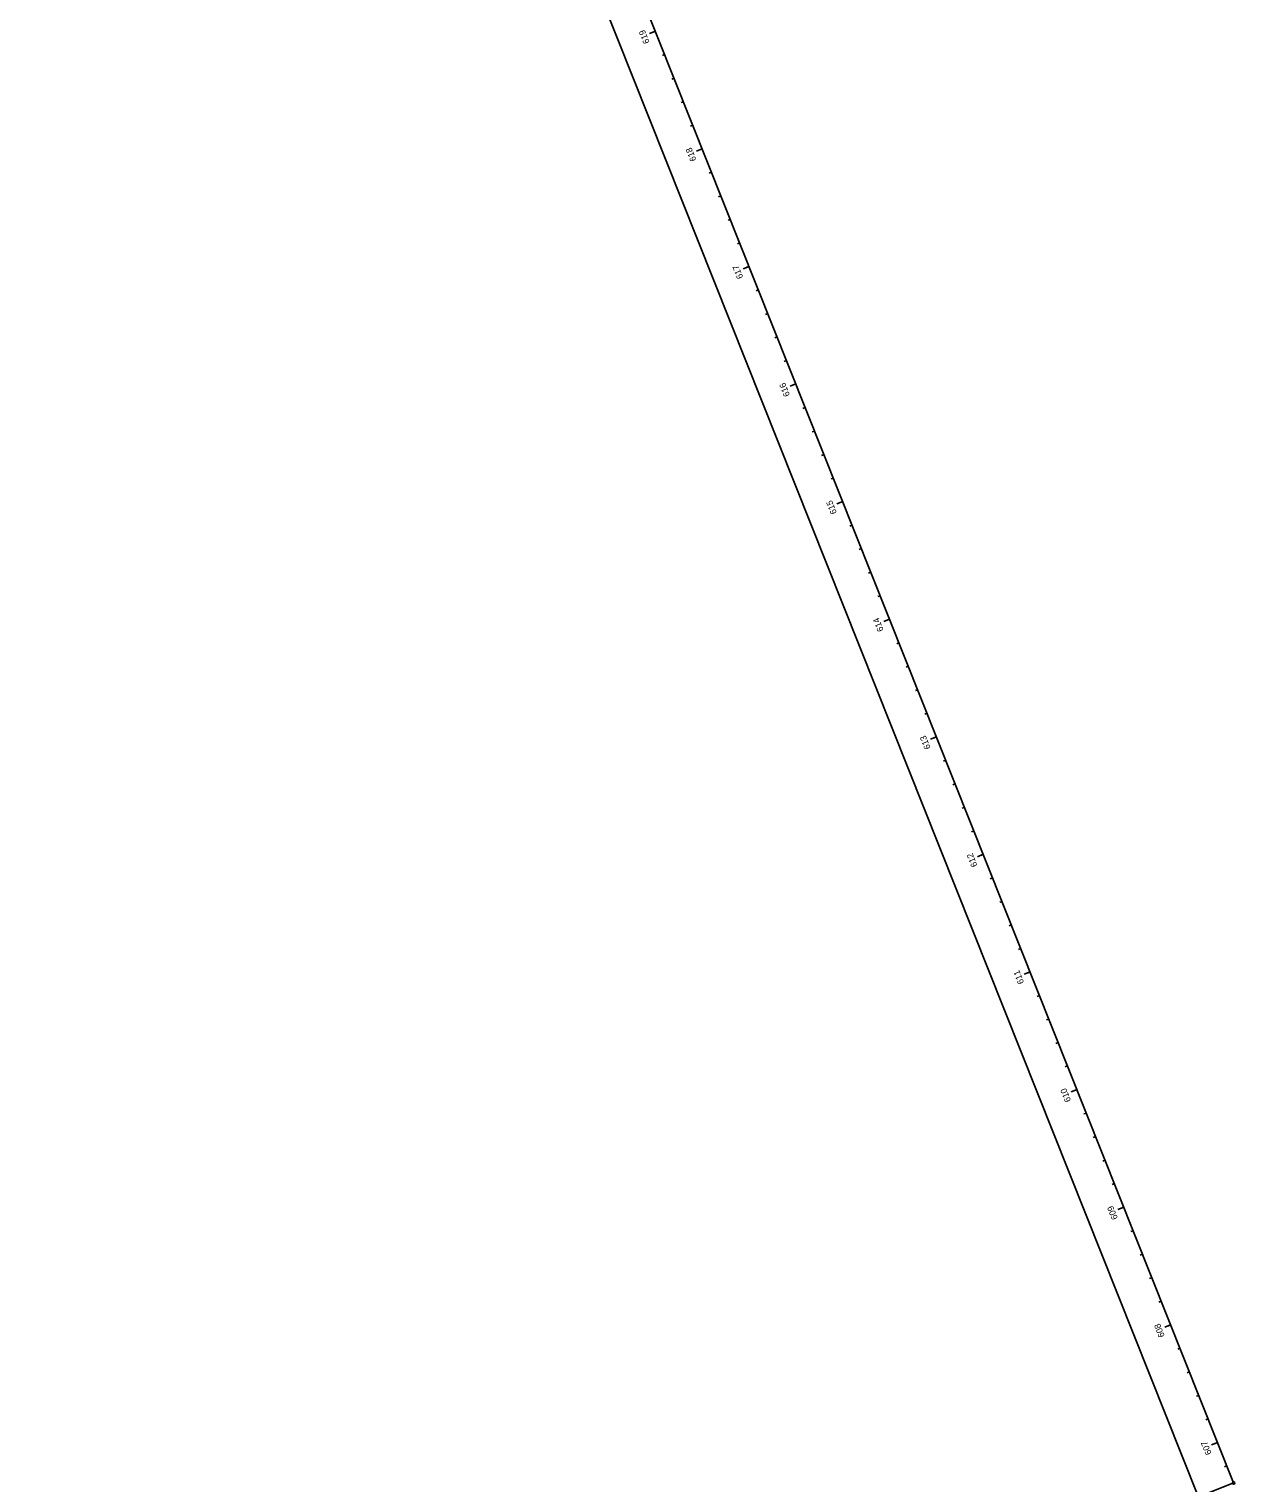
# Model space of a CAD drawing. Extents: x 2003883 to 2007688, y 399149 to 412300.
# Drawn here: x 2004016 to 2004969, y 407935 to 409083 of the extents above; entities that cross this region are included whole.
import ezdxf

# ---------------------------------------------------------------- set-up
doc = ezdxf.new("R2010")
doc.units = 0
for name, color, linetype in [('BaselineSurvey', 7, 'Continuous'), ('DataBoxWt2', 7, 'Continuous'), ('Default', 7, 'Continuous'), ('EaseLine_ep', 7, 'Continuous'), ('PropertyLine_ep', 7, 'Continuous'), ('PropertyLineHook_ep', 7, 'Continuous'), ('PropertyLineSymbol_ep', 7, 'Continuous'), ('SubDivLineText', 7, 'Continuous'), ('SubLotNumberText', 7, 'Continuous'), ('SubVacOrigLotStaTie', 7, 'Continuous'), ('TextMisc', 7, 'Continuous')]:
    doc.layers.add(name, color=color, linetype=linetype)

msp = doc.modelspace()

# ---------------------------------------------------------------- linework, layer by layer
at = {"layer": 'DataBoxWt2'}
for p, q in [((2004547.7, 408988.9), (2004545.9, 408988.2)), ((2004621.8, 408803.2), (2004619.9, 408802.4)), ((2004695.8, 408617.4), (2004694, 408616.6)), ((2004769.8, 408431.6), (2004768, 408430.8)), ((2004843.9, 408245.8), (2004839.2, 408243.9)), ((2004917.9, 408060), (2004916.1, 408059.2))]:
    msp.add_line(p, q, dxfattribs=at)
at = {"layer": 'Default'}
msp.add_line((2004967.7, 407935), (2004043.6, 410254), dxfattribs=at)
at = {"layer": 'EaseLine_ep'}
msp.add_line((2004939.8, 407923.9), (2004015.7, 410242.9), dxfattribs=at)
at = {"layer": 'PropertyLine_ep'}
msp.add_line((2004967.7, 407935), (2004043.6, 410254), dxfattribs=at)
at = {"layer": 'PropertyLineHook_ep'}
for p, q in [((2004510.7, 409081.8), (2004506.1, 409080)), ((2004518.1, 409063.3), (2004516.3, 409062.5)), ((2004525.5, 409044.7), (2004523.7, 409043.9)), ((2004532.9, 409026.1), (2004531.1, 409025.4)), ((2004540.3, 409007.5), (2004538.5, 409006.8)), ((2004547.7, 408988.9), (2004543.1, 408987.1)), ((2004555.1, 408970.4), (2004553.3, 408969.6)), ((2004562.5, 408951.8), (2004560.7, 408951)), ((2004569.9, 408933.2), (2004568.1, 408932.5)), ((2004577.4, 408914.6), (2004575.5, 408913.9)), ((2004584.8, 408896), (2004580.1, 408894.2)), ((2004592.2, 408877.5), (2004590.3, 408876.7)), ((2004599.6, 408858.9), (2004597.7, 408858.1)), ((2004607, 408840.3), (2004605.1, 408839.6)), ((2004614.4, 408821.7), (2004612.5, 408821)), ((2004621.8, 408803.2), (2004617.1, 408801.3)), ((2004629.2, 408784.6), (2004627.3, 408783.8)), ((2004636.6, 408766), (2004634.7, 408765.3)), ((2004644, 408747.4), (2004642.1, 408746.7)), ((2004651.4, 408728.8), (2004649.5, 408728.1)), ((2004658.8, 408710.3), (2004654.1, 408708.4)), ((2004666.2, 408691.7), (2004664.3, 408690.9)), ((2004673.6, 408673.1), (2004671.7, 408672.4)), ((2004681, 408654.5), (2004679.1, 408653.8)), ((2004688.4, 408635.9), (2004686.6, 408635.2)), ((2004695.8, 408617.4), (2004691.2, 408615.5)), ((2004703.2, 408598.8), (2004701.4, 408598)), ((2004710.6, 408580.2), (2004708.8, 408579.5)), ((2004718, 408561.6), (2004716.2, 408560.9)), ((2004725.4, 408543), (2004723.6, 408542.3)), ((2004732.8, 408524.5), (2004728.2, 408522.6)), ((2004740.2, 408505.9), (2004738.4, 408505.1)), ((2004747.6, 408487.3), (2004745.8, 408486.6)), ((2004755, 408468.7), (2004753.2, 408468)), ((2004762.4, 408450.1), (2004760.6, 408449.4)), ((2004769.8, 408431.6), (2004765.2, 408429.7)), ((2004777.3, 408413), (2004775.4, 408412.2)), ((2004784.7, 408394.4), (2004782.8, 408393.7)), ((2004792.1, 408375.8), (2004790.2, 408375.1)), ((2004799.5, 408357.3), (2004797.6, 408356.5)), ((2004806.9, 408338.7), (2004802.2, 408336.8)), ((2004814.3, 408320.1), (2004812.4, 408319.4)), ((2004821.7, 408301.5), (2004819.8, 408300.8)), ((2004829.1, 408282.9), (2004827.2, 408282.2)), ((2004836.5, 408264.4), (2004834.6, 408263.6)), ((2004843.9, 408245.8), (2004839.2, 408243.9)), ((2004851.3, 408227.2), (2004849.4, 408226.5)), ((2004858.7, 408208.6), (2004856.8, 408207.9)), ((2004866.1, 408190), (2004864.2, 408189.3)), ((2004873.5, 408171.5), (2004871.6, 408170.7)), ((2004880.9, 408152.9), (2004876.3, 408151)), ((2004888.3, 408134.3), (2004886.5, 408133.6)), ((2004895.7, 408115.7), (2004893.9, 408115)), ((2004903.1, 408097.1), (2004901.3, 408096.4)), ((2004910.5, 408078.6), (2004908.7, 408077.8)), ((2004917.9, 408060), (2004913.3, 408058.1)), ((2004925.3, 408041.4), (2004923.5, 408040.7)), ((2004932.7, 408022.8), (2004930.9, 408022.1)), ((2004940.1, 408004.2), (2004938.3, 408003.5)), ((2004947.5, 407985.7), (2004945.7, 407984.9)), ((2004954.9, 407967.1), (2004950.3, 407965.2)), ((2004962.3, 407948.5), (2004960.5, 407947.8))]:
    msp.add_line(p, q, dxfattribs=at)
at = {"layer": 'SubDivLineText'}
for p, q in [((2004510.7, 409081.8), (2004508.9, 409081.1)), ((2004547.7, 408988.9), (2004545.9, 408988.2)), ((2004584.8, 408896), (2004582.9, 408895.3)), ((2004621.8, 408803.2), (2004619.9, 408802.4)), ((2004658.8, 408710.3), (2004654.1, 408708.4)), ((2004695.8, 408617.4), (2004694, 408616.6)), ((2004732.8, 408524.5), (2004731, 408523.7)), ((2004769.8, 408431.6), (2004768, 408430.8)), ((2004806.9, 408338.7), (2004805, 408337.9)), ((2004843.9, 408245.8), (2004839.2, 408243.9)), ((2004880.9, 408152.9), (2004879, 408152.1)), ((2004917.9, 408060), (2004916.1, 408059.2)), ((2004954.9, 407967.1), (2004953.1, 407966.3))]:
    msp.add_line(p, q, dxfattribs=at)
at = {"layer": 'SubVacOrigLotStaTie'}
msp.add_line((2004843.9, 408245.8), (2004842, 408245), dxfattribs=at)
at = {"layer": 'TextMisc'}
msp.add_line((2004967.7, 407935), (2004907.3, 407911), dxfattribs=at)
msp.add_circle((2004967.7, 407935), 1, dxfattribs=at)

# ---------------------------------------------------------------- texts
at = {"layer": 'BaselineSurvey'}
msp.add_text('610', height=4.98, rotation=111.7271, dxfattribs=at).set_placement((2004839.3, 408237))
at = {"layer": 'PropertyLineSymbol_ep'}
for s, p in [('619', (2004506.2, 409073)), ('618', (2004543.2, 408980.1)), ('617', (2004580.2, 408887.3)), ('616', (2004617.2, 408794.3)), ('615', (2004654.2, 408701.4)), ('614', (2004691.2, 408608.6)), ('613', (2004728.3, 408515.6)), ('612', (2004765.3, 408422.7)), ('611', (2004802.2, 408330.2)), ('610', (2004839.3, 408237)), ('609', (2004876.3, 408144.1)), ('608', (2004913.4, 408051.1)), ('607', (2004950.4, 407958.3))]:
    msp.add_text(s, height=4.98, rotation=111.7271, dxfattribs=at).set_placement(p)
at = {"layer": 'SubLotNumberText'}
for s, p in [('615', (2004654.2, 408701.4)), ('610', (2004839.3, 408237))]:
    msp.add_text(s, height=4.98, rotation=111.7271, dxfattribs=at).set_placement(p)

doc.saveas('drawing.dxf')
